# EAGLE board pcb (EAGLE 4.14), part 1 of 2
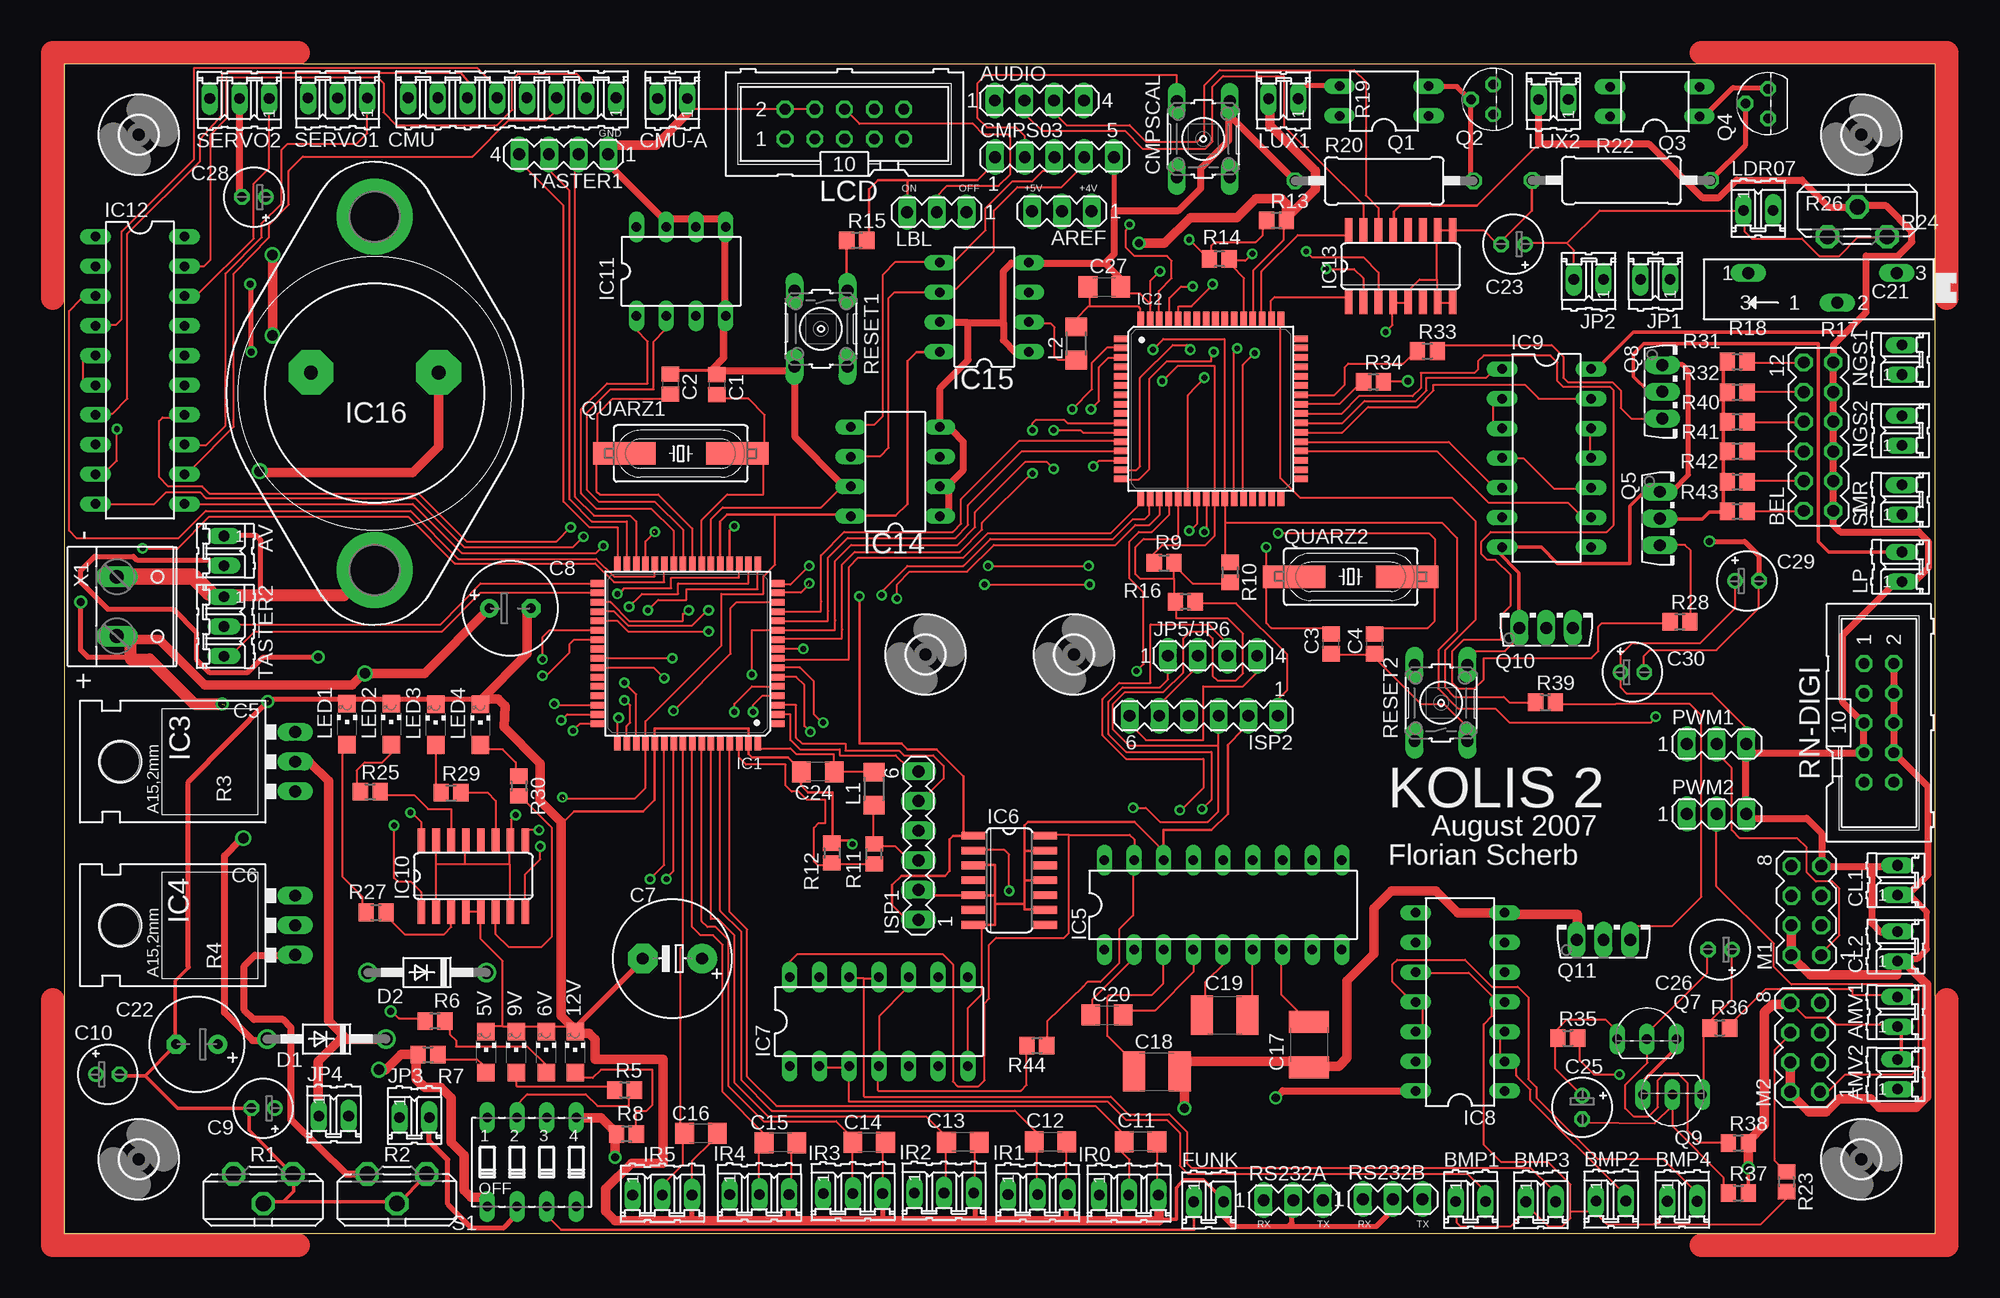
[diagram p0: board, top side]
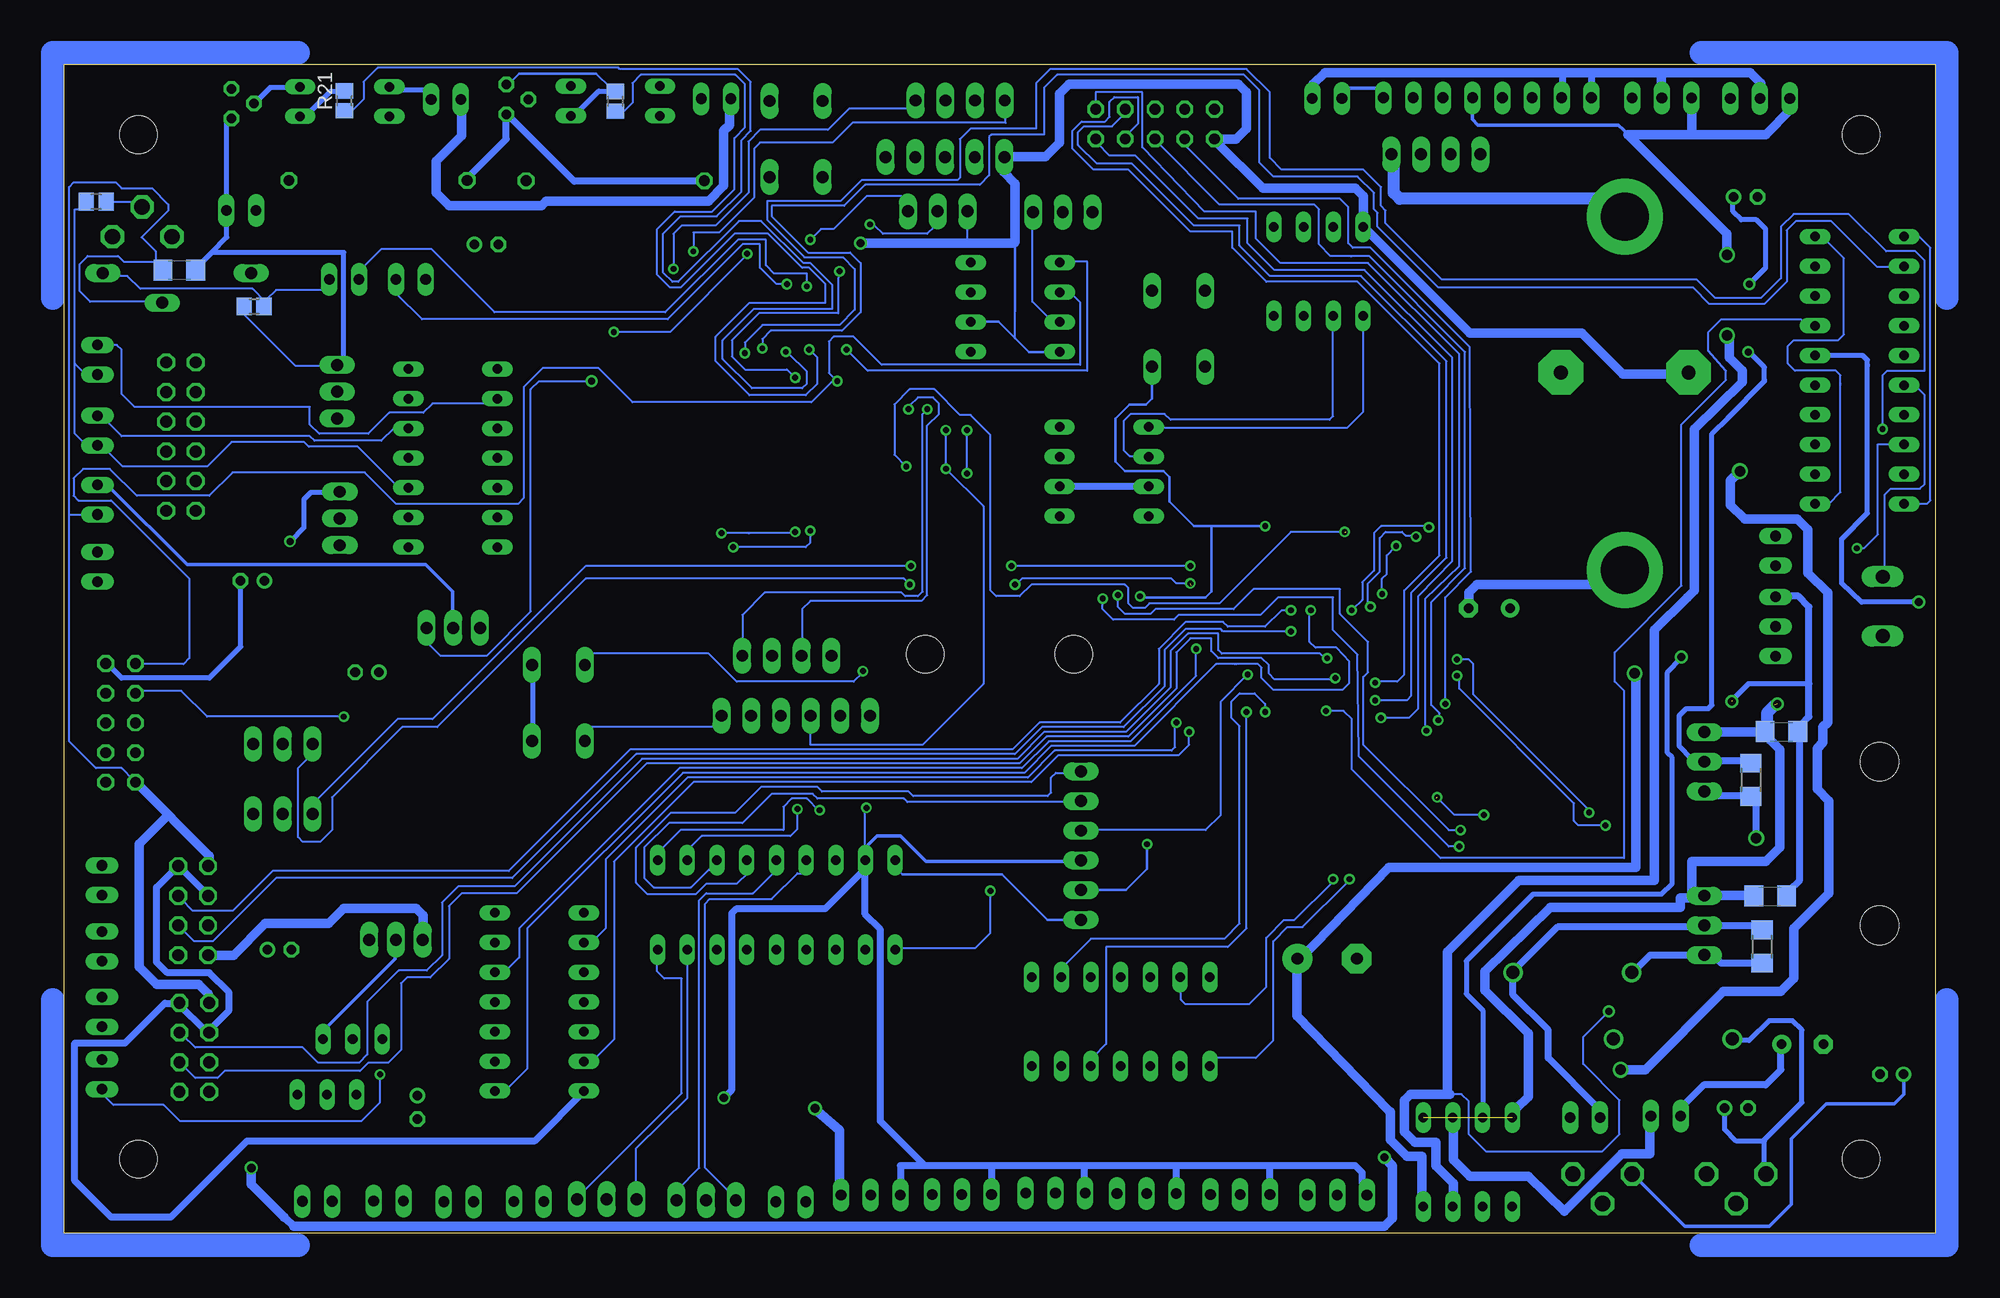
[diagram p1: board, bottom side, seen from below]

Size 160 x 100 mm. Coordinates in mm from the lower left corner, seen from the top.
Outline: 0,0 160,0 160,100 0,100 0,0
Copper layers (1*16): Top 0.035mm / dielectric 1.5mm / Bottom 0.035mm
Design rules "rnbfra1": minimum track width 12mil, minimum drill 24mil, track to track 10mil, track to pad 10mil, pad to pad 10mil, via to via 8mil, smd to smd 8mil, copper to edge 40mil, drill to drill 8mil, minimum pad ring 10mil, minimum via ring 8mil, stop-mask expansion 4mil, vias tented up to drill 0mil, thermal gap 10mil
Net classes: 1 Power4A: width 1.143 mm; 2 Power2A: width 0.762 mm; 3 Power3A: width 1.016 mm

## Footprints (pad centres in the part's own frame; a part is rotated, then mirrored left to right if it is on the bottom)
CHIPLED_1206 = smd 1.5 x 1.5: A 0,-1.75; C 0,1.75
02P = drill 0.914 long: 1 -1.27,0; 2 1.27,0
MA03-1 = drill 1.016 long: 1 -2.54,0; 2 0,0; 3 2.54,0
MA04-1 = drill 1.016 long: 1 -3.81,0; 2 -1.27,0; 3 1.27,0; 4 3.81,0
MA06-2 = drill 1.016 octagon: 1 -6.35,-1.27; 2 -6.35,1.27; 3 -3.81,-1.27; 4 -3.81,1.27; 5 -1.27,-1.27; 6 -1.27,1.27; 7 1.27,-1.27; 8 1.27,1.27; 9 3.81,-1.27; 10 3.81,1.27; 11 6.35,-1.27; 12 6.35,1.27
C0805 = smd 1.3 x 1.5: 1 -0.85,0; 2 0.85,0
C1206 = smd 1.6 x 1.8: 1 -1.4,0; 2 1.4,0
E5-10,5 = drill 1.016 pad 2.54 round: + -2.54,0 | drill 1.016 pad 2.54 octagon: - 2.54,0
E3,5-8 = drill 0.813 pad 1.6 round: + -1.778,0 | drill 0.813 pad 1.6 octagon: - 1.778,0
E2-5 = drill 0.813 pad 1.27 round: + -1.016,0 | drill 0.813 pad 1.27 octagon: - 1.016,0
C1812 = smd 1.9 x 3.4: 1 -1.95,0; 2 1.95,0
MA05-1 = drill 1.016 long: 1 -5.08,0; 2 -2.54,0; 3 0,0; 4 2.54,0; 5 5.08,0
B3F-10XX = drill 1.016 long: 1 -3.251,2.261; 2 3.251,2.261; 3 -3.251,-2.261; 4 3.251,-2.261
08P = drill 0.914 long: 1 -8.89,0; 2 -6.35,0; 3 -3.81,0; 4 -1.27,0; 5 1.27,0; 6 3.81,0; 7 6.35,0; 8 8.89,0
DO41-10 = drill 1.118 round: A 5.08,0; C -5.08,0
TQFP64-AEB = smd 1.194 x 0.559: 1 -7.7,6; 2 -7.7,5.2; 3 -7.7,4.4; 4 -7.7,3.6; 5 -7.7,2.8; 6 -7.7,2; 7 -7.7,1.2; 8 -7.7,0.4; 9 -7.7,-0.4; 10 -7.7,-1.2; 11 -7.7,-2; 12 -7.7,-2.8; 13 -7.7,-3.6; 14 -7.7,-4.4; 15 -7.7,-5.2; 16 -7.7,-6; 33 7.7,-6; 34 7.7,-5.2; 35 7.7,-4.4; 36 7.7,-3.6; 37 7.7,-2.8; 38 7.7,-2; 39 7.7,-1.2; 40 7.7,-0.4; 41 7.7,0.4; 42 7.7,1.2; 43 7.7,2; 44 7.7,2.8; 45 7.7,3.6; 46 7.7,4.4; 47 7.7,5.2; 48 7.7,6 | smd 0.559 x 1.194: 17 -6,-7.7; 18 -5.2,-7.7; 19 -4.4,-7.7; 20 -3.6,-7.7; 21 -2.8,-7.7; 22 -2,-7.7; 23 -1.2,-7.7; 24 -0.4,-7.7; 25 0.4,-7.7; 26 1.2,-7.7; 27 2,-7.7; 28 2.8,-7.7; 29 3.6,-7.7; 30 4.4,-7.7; 31 5.2,-7.7; 32 6,-7.7; 49 6,7.7; 50 5.2,7.7; 51 4.4,7.7; 52 3.6,7.7; 53 2.8,7.7; 54 2,7.7; 55 1.2,7.7; 56 0.4,7.7; 57 -0.4,7.7; 58 -1.2,7.7; 59 -2,7.7; 60 -2.8,7.7; 61 -3.6,7.7; 62 -4.4,7.7; 63 -5.2,7.7; 64 -6,7.7
317TL = drill 1.016 long: 1 -2.54,-3.81; 2 0,-3.81; 3 2.54,-3.81 | hole 3.302: 0,11.176
DIL18 = drill 0.813 long: 1 -10.16,-3.81; 2 -7.62,-3.81; 3 -5.08,-3.81; 4 -2.54,-3.81; 5 0,-3.81; 6 2.54,-3.81; 7 5.08,-3.81; 8 7.62,-3.81; 9 10.16,-3.81; 10 10.16,3.81; 11 7.62,3.81; 12 5.08,3.81; 13 2.54,3.81; 14 0,3.81; 15 -2.54,3.81; 16 -5.08,3.81; 17 -7.62,3.81; 18 -10.16,3.81
SO14 = smd 0.66 x 2.032: 1 -3.81,-3.073; 2 -2.54,-3.073; 3 -1.27,-3.073; 4 0,-3.073; 5 1.27,-3.073; 6 2.54,-3.073; 7 3.81,-3.073; 8 3.81,3.073; 9 2.54,3.073; 10 1.27,3.073; 11 0,3.073; 12 -1.27,3.073; 13 -2.54,3.073; 14 -3.81,3.073
DIL14 = drill 0.813 long: 1 -7.62,-3.81; 2 -5.08,-3.81; 3 -2.54,-3.81; 4 0,-3.81; 5 2.54,-3.81; 6 5.08,-3.81; 7 7.62,-3.81; 8 7.62,3.81; 9 5.08,3.81; 10 2.54,3.81; 11 0,3.81; 12 -2.54,3.81; 13 -5.08,3.81; 14 -7.62,3.81
SO16 = smd 0.66 x 2.032: 1 -4.445,-3.073; 2 -3.175,-3.073; 3 -1.905,-3.073; 4 -0.635,-3.073; 5 0.635,-3.073; 6 1.905,-3.073; 7 3.175,-3.073; 8 4.445,-3.073; 9 4.445,3.073; 10 3.175,3.073; 11 1.905,3.073; 12 0.635,3.073; 13 -0.635,3.073; 14 -1.905,3.073; 15 -3.175,3.073; 16 -4.445,3.073
DIL08 = drill 0.813 long: 1 -3.81,-3.81; 2 -1.27,-3.81; 3 1.27,-3.81; 4 3.81,-3.81; 5 3.81,3.81; 6 1.27,3.81; 7 -1.27,3.81; 8 -3.81,3.81
DIL20 = drill 0.813 long: 1 -11.43,-3.81; 2 -8.89,-3.81; 3 -6.35,-3.81; 4 -3.81,-3.81; 5 -1.27,-3.81; 6 1.27,-3.81; 7 3.81,-3.81; 8 6.35,-3.81; 9 8.89,-3.81; 10 11.43,-3.81; 11 11.43,3.81; 12 8.89,3.81; 13 6.35,3.81; 14 3.81,3.81; 15 1.27,3.81; 16 -1.27,3.81; 17 -3.81,3.81; 18 -6.35,3.81; 19 -8.89,3.81; 20 -11.43,3.81
DIL8 = drill 0.813 long: 1 -3.81,-3.81; 2 -1.27,-3.81; 3 1.27,-3.81; 4 3.81,-3.81; 5 3.81,3.81; 6 1.27,3.81; 7 -1.27,3.81; 8 -3.81,3.81
TO3-K02 = drill 1.194 pad 3.81 octagon: 1 -1.778,-5.461; 2 -1.778,5.461 | drill 4.115 pad 6.477 round: 3 15.113,0; 3@ -15.113,0
03P = drill 0.914 long: 1 -2.54,0; 2 0,0; 3 2.54,0
MA06-1 = drill 1.016 long: 1 -6.35,0; 2 -3.81,0; 3 -1.27,0; 4 1.27,0; 5 3.81,0; 6 6.35,0
R1206 = smd 1.6 x 1.803: 1 -1.422,0; 2 1.422,0
ML10 = drill 0.914 octagon: 1 -5.08,-1.27; 2 -5.08,1.27; 3 -2.54,-1.27; 4 -2.54,1.27; 5 0,-1.27; 6 0,1.27; 7 2.54,-1.27; 8 2.54,1.27; 9 5.08,-1.27; 10 5.08,1.27
MA04-2 = drill 1.016 octagon: 1 -3.81,-1.27; 2 -3.81,1.27; 3 -1.27,-1.27; 4 -1.27,1.27; 5 1.27,-1.27; 6 1.27,1.27; 7 3.81,-1.27; 8 3.81,1.27
DIL04 = drill 0.813 long: 1 -1.27,-3.81; 2 1.27,-3.81; 3 1.27,3.81; 4 -1.27,3.81
TO92 = drill 0.813 octagon: 1 1.27,0; 2 0,1.905; 3 -1.27,0
TO126AV = drill 1.016 long: B 2.286,-1.27; C 0,-1.27; E -2.286,-1.27
TO92-EBC = drill 0.813 long: B 0,-1.27; C -2.54,-1.27; E 2.54,-1.27
HC49UP = smd 5.334 x 1.93: 1 -4.826,0; 2 4.826,0
ST10 = drill 1.321 octagon: A -2.54,-1.27; E 2.54,-1.27; S 0,1.27
R0805 = smd 1.3 x 1.5: 1 -0.85,0; 2 0.85,0
SP19L = drill 1.016 long: A 5.715,-1.27; E -6.985,-1.27; S -1.905,1.27
0411/15 = drill 0.914 octagon: 1 -7.62,0; 2 7.62,0
DIP04S = drill 0.813 long: 1 -3.81,-3.81; 2 -1.27,-3.81; 3 1.27,-3.81; 4 3.81,-3.81; 5 3.81,3.81; 6 1.27,3.81; 7 -1.27,3.81; 8 -3.81,3.81
3,2 = hole 3.2: 0,0
W237-132 = drill 1.194 long: 1 -2.54,-0.635; 2 2.54,-0.635

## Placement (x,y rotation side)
5V  [CHIPLED_1206]  36.07,15.52 0 top
6V  [CHIPLED_1206]  41.21,15.52 0 top
9V  [CHIPLED_1206]  38.65,15.52 0 top
12V  [CHIPLED_1206]  43.69,15.52 0 top
AMV1  [02P]  156.77,18.95 90 top
AMV2  [02P]  156.77,13.61 90 top
AREF  [MA03-1]  85.31,87.43 180 top
AUDIO  [MA04-1]  83.38,96.91 0 top
AV  [02P]  13.64,58.38 270 top
BEL  [MA06-2]  150.02,68.16 90 top
BMP1  [02P]  120.27,2.73 0 top
BMP2  [02P]  132.27,2.77 0 top
BMP3  [02P]  126.27,2.71 0 top
BMP4  [02P]  138.37,2.75 0 top
C1  [C0805]  55.82,72.6 270 top
C2  [C0805]  51.83,72.65 270 top
C3  [C0805]  108.33,50.43 90 top
C4  [C0805]  112.05,50.43 90 top
C5  100n  [C1206]  13.15,42.93 0 bottom
C6  100n  [C1206]  14.11,28.86 0 bottom
C7  1m  [E5-10,5]  52.01,23.51 180 top
C8  330µ  [E3,5-8]  38.14,53.47 0 top
C9  10µ  [E2-5]  17.01,10.71 180 top
C10  10µ  [E2-5]  3.71,13.61 0 top
C11  100n  [C1206]  92.04,7.85 180 top
C12  100n  [C1206]  84.34,7.83 180 top
C13  100n  [C1206]  76.84,7.81 180 top
C14  100n  [C1206]  68.84,7.79 180 top
C15  100n  [C1206]  61.24,7.77 180 top
C16  100n  [C1206]  54.44,8.55 180 top
C17  330n  [C1812]  106.44,16.15 270 top
C18  330n  [C1812]  93.44,13.86 0 top
C19  330n  [C1812]  99.24,18.67 0 top
C20  47n  [C1206]  89.17,18.68 0 top
C21  100n  [C1206]  150.17,82.4 0 bottom
C22  330µ  [E3,5-8]  11.34,16.18 180 top
C23  47µ  [E2-5]  123.91,84.61 180 top
C24  100n  [C1206]  64.44,39.48 180 top
C25  47µ  [E2-5]  129.81,10.78 270 top
C26  47µ  [E2-5]  141.61,24.28 180 top
C27  100n  [C1206]  88.94,80.96 0 top
C28  47µ  [E2-5]  16.21,88.64 180 top
C29  47µ  [E2-5]  143.91,55.81 0 top
C30  47µ  [E2-5]  134.11,48.01 0 top
CL1  [02P]  156.77,30.21 90 top
CL2  [02P]  156.77,24.55 90 top
CMPS03  [MA05-1]  84.68,92.07 0 top
CMPSCAL  [B3F-10XX]  97.41,93.61 90 top
CMU  [08P]  38.29,97.14 180 top
CMU-A  [02P]  52.01,97.08 180 top
D1  1N4002  [DO41-10]  22.43,16.63 180 top
D2  1N4002  [DO41-10]  31.03,22.32 180 top
FUNK  [02P]  97.87,2.7 0 top
IC1  MEGA128-A  [TQFP64-AEB]  53.31,49.59 180 top
IC2  MEGA128-B  [TQFP64-AEB]  98.05,70.53 0 top
IC3  LM317-6V  [317TL]  15.94,40.35 90 top
IC4  LM317-9V  [317TL]  15.94,26.35 90 top
IC5  MAX3222  [DIL18]  99.1,28.1 0 top
IC6  74HC04  [SO14]  80.81,30.21 270 top
IC7  74HC74  [DIL14]  69.66,18.12 0 top
IC8  74HC74  [DIL14]  119.36,19.8 90 top
IC9  74HC74  [DIL14]  126.76,66.32 270 top
IC10  MAX392  [SO16]  34.98,30.57 0 top
IC11  DS1621  [DIL08]  52.75,82.3 0 top
IC12  MAX333  [DIL20]  6.47,73.83 270 top
IC13  MAX392  [SO16]  114.28,82.74 0 top
IC14  AT24C512  [DIL8]  71.08,65.17 90 top
IC15  AT24C512  [DIL8]  78.68,79.23 90 top
IC16  LM323K  [TO3-K02]  26.55,71.86 270 top
IR0  [03P]  91.04,3.28 0 top
IR1  [03P]  83.24,3.32 0 top
IR2  [03P]  75.24,3.46 0 top
IR3  [03P]  67.44,3.4 0 top
IR4  [03P]  59.44,3.34 0 top
IR5  [03P]  51.14,3.28 0 top
ISP1  [MA06-1]  73.05,33.18 90 top
ISP2  [MA06-1]  97.45,44.28 180 top
JP1  [02P]  136.07,81.61 180 top
JP2  [02P]  130.37,81.59 180 top
JP3  [02P]  29.94,9.91 0 top
JP4  [02P]  23.04,10.05 0 top
JP5/JP6  [MA04-1]  98.21,49.41 0 top
L1  10µH  [R1206]  69.24,38.04 90 top
L2  10µH  [R1206]  86.54,76.12 90 top
LBL  [MA03-1]  74.61,87.35 180 top
LCD  [ML10]  66.72,94.89 0 top
LDR07  [02P]  144.87,87.51 0 top
LED1  [CHIPLED_1206]  24.18,43.57 0 top
LED2  [CHIPLED_1206]  27.96,43.57 0 top
LED3  [CHIPLED_1206]  31.76,43.53 0 top
LED4  [CHIPLED_1206]  35.58,43.53 0 top
LP  [02P]  157.17,57.02 90 top
LUX1  [02P]  104.26,97.05 180 top
LUX2  [02P]  127.36,96.99 180 top
M1  [MA04-2]  148.98,27.61 90 top
M2  [MA04-2]  148.88,15.91 90 top
NGS1  [02P]  157.17,74.73 90 top
NGS2  [02P]  157.17,68.67 90 top
PWM1  [MA03-1]  141.31,41.86 0 top
PWM2  [MA03-1]  141.31,35.88 0 top
Q1  IRFD024  [DIL04]  112.86,96.86 90 top
Q2  BC547B  [TO92]  122.2,97 90 top
Q3  IRFD024  [DIL04]  136.02,96.81 90 top
Q4  BC547B  [TO92]  145.69,96.64 90 top
Q5  BD139  [TO126AV]  137.71,61.15 270 top
Q7  BC548B  [TO92-EBC]  135.34,17.88 0 top
Q8  BD139  [TO126AV]  137.94,71.99 270 top
Q9  BC548B  [TO92-EBC]  137.54,10.59 180 top
Q10  BD139  [TO126AV]  126.74,53.07 0 top
Q11  BD139  [TO126AV]  131.64,26.39 0 top
QUARZ1  14,5467MHz  [HC49UP]  52.72,66.71 0 top
QUARZ2  14,5467MHz  [HC49UP]  110.02,56.18 0 top
R1  10k  [ST10]  17.02,3.81 180 top
R2  10k  [ST10]  28.45,3.81 180 top
R3  240  [R1206]  15.75,38.81 90 bottom
R4  240  [R1206]  14.81,24.54 90 bottom
R5  240  [R0805]  47.9,12.28 0 top
R6  130  [R0805]  31.7,18.16 180 top
R7  330  [R0805]  31.1,15.3 0 top
R8  330  [R0805]  48.07,8.5 180 top
R9  4,7k  [R0805]  94.05,57.35 0 top
R10  4,7k  [R0805]  99.7,56.55 270 top
R11  1k  [R0805]  69.25,32.46 90 top
R12  2,2k  [R0805]  65.65,32.53 270 top
R13  1k  [R0805]  103.67,86.65 0 top
R14  3,9k  [R0805]  98.77,83.35 180 top
R15  47k  [R0805]  67.77,84.95 0 top
R16  47k  [R0805]  95.87,54.03 180 top
R17  10k  [SP19L]  149.73,80.88 180 top
R18  10k  [R0805]  143.77,79.29 0 bottom
R19  10k  [R0805]  112.86,96.83 90 bottom
R20  0,75  [0411/15]  112.88,90.04 0 top
R21  10k  [R0805]  136.05,96.87 90 bottom
R22  0,75  [0411/15]  133.17,90.08 0 top
R23  10k  [R0805]  147.27,4.43 270 top
R24  10k  [R0805]  157.27,88.25 180 bottom
R25  130  [R0805]  26.17,37.78 0 top
R26  25k  [ST10]  153.34,86.53 0 top
R27  130  [R0805]  26.67,27.46 0 top
R28  1k  [R0805]  138.17,52.33 0 top
R29  130  [R0805]  33.07,37.68 0 top
R30  130  [R0805]  38.87,38.26 270 top
R31  150  [R0805]  143.07,74.57 0 top
R32  150  [R0805]  143.07,71.95 0 top
R33  1k  [R0805]  116.57,75.47 0 top
R34  1k  [R0805]  111.97,72.85 0 top
R35  1k  [R0805]  128.57,16.7 0 top
R36  1k  [R0805]  141.57,17.58 0 top
R37  47k  [R0805]  143.17,3.46 0 top
R38  47k  [R0805]  143.17,7.74 0 top
R39  1k  [R0805]  126.67,45.43 0 top
R40  150  [R0805]  143.07,69.43 0 top
R41  150  [R0805]  143.07,66.91 0 top
R42  150  [R0805]  143.07,64.29 0 top
R43  150  [R0805]  143.07,61.77 0 top
R44  10k  [R0805]  83.17,16.05 180 top
RESET1  [B3F-10XX]  64.71,77.38 270 top
RESET2  [B3F-10XX]  117.74,45.38 90 top
RN-DIGI  [ML10]  155.19,43.67 270 top
RS232A  [MA03-1]  105.11,2.85 0 top
RS232B  [MA03-1]  113.61,2.93 0 top
S1  [DIP04S]  39.98,6.1 0 top
SERVO1  [03P]  23.38,97.12 180 top
SERVO2  [03P]  14.98,97.08 180 top
SMR  [02P]  157.17,62.76 90 top
TASTER1  [MA04-1]  42.71,92.3 180 top
TASTER2  [03P]  13.64,51.91 270 top
U$3  [3,2]  6.35,6.35 0 top
U$5  [3,2]  6.35,93.98 0 top
U$6  [3,2]  86.36,49.53 0 top
U$7  [3,2]  73.66,49.53 0 top
U$8  [3,2]  153.67,93.98 0 top
U$9  [3,2]  153.67,6.35 0 top
X1  [W237-132]  5.13,53.63 270 top

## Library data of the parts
5V 6V 9V 12V LED1-LED4 = led
AMV1 AMV2 AV BMP1-BMP4 CL1 CL2 CMU CMU-A FUNK IR0 IR1-IR5 JP1-JP4 LDR07 LP LUX1 LUX2 NGS1 NGS2 SERVO1 SERVO2 SMR TASTER2 = con-amp-quick
AREF AUDIO BEL CMPS03 ISP1 ISP2 JP5/JP6 LBL M1 M2 PWM1 PWM2 RS232A RS232B TASTER1 = con-lstb
C1-C30 L1 L2 R3-R16 R18-R25 R27-R44 = rcl
CMPSCAL RESET1 RESET2 = switch-omron
D1 D2 = diode
IC1 IC2 = atmel
IC3 IC4 IC16 = v-reg
IC5 = TBKMaxim
IC6-IC9 = 74xx-eu
IC10 IC12 IC13 = maxim
IC11 = atmel-flash
IC14 IC15 = microchip
LCD RN-DIGI = con-harting-ml
Q1 Q3 = transistor-fet
Q2 Q4 Q7 Q9 = transistor-npn
Q5 Q8 Q10 Q11 = transistor-power
QUARZ1 QUARZ2 = crystal
R1 R2 R17 R26 = pot
S1 = switch-dil
U$3 U$5-U$9 = holes
X1 = con-wago-508

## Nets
S$16: S1.5 S1.8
